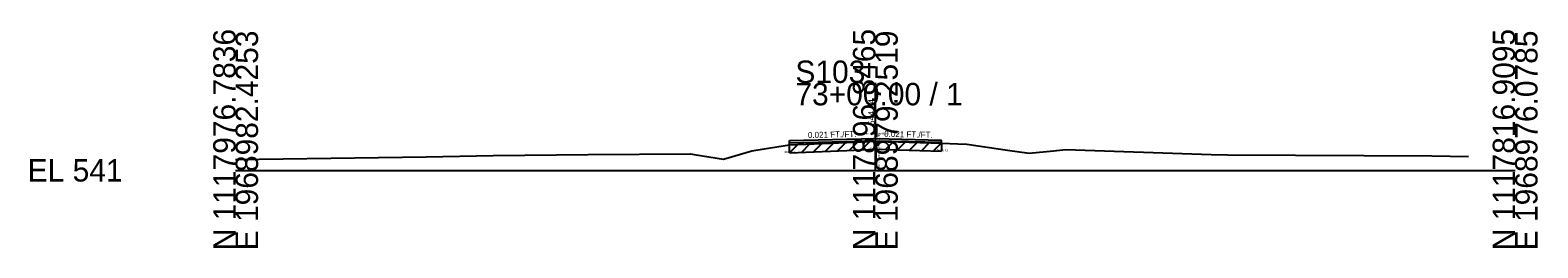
# Model space of a CAD drawing. Extents: x -26 to 163, y -10 to 24018.
# Drawn here: x -25.7 to 162.8, y 20990.3 to 21017.5 of the extents above; entities that cross this region are included whole.
import ezdxf

# ---------------------------------------------------------------- set-up
doc = ezdxf.new("R2010")
doc.units = 0
for name, color, linetype in [('RD_GPK_XS_Cell', 7, 'Continuous'), ('RD_XS_ExGround', 7, 'Continuous'), ('RD_XS_ExPaveRet', 7, 'Continuous'), ('RD_XS_Misc_Line', 7, 'Continuous'), ('RD_XS_PaveOvlay_CP', 7, 'Continuous'), ('RD_XS_TX_Elev_EX', 7, 'Continuous'), ('RD_XS_TX_ExEOP', 7, 'Continuous'), ('RD_XS_TX_Notes', 7, 'Continuous'), ('RD_XS_TX_Profile', 7, 'Continuous'), ('RD_XS_TX_Slope', 7, 'Continuous')]:
    doc.layers.add(name, color=color, linetype=linetype)

msp = doc.modelspace()

# ---------------------------------------------------------------- linework, layer by layer
at = {"layer": 'RD_GPK_XS_Cell'}
for p, q in [((80, 21000), (80, 21010.93)), ((0, 21000), (80, 21000)), ((80, 21000), (160, 21000))]:
    msp.add_line(p, q, dxfattribs=at)
at = {"layer": 'RD_XS_ExGround'}
msp.add_lwpolyline([(0, 21001.37), (23.84, 21001.68), (32.19, 21001.85), (44.07, 21002), (56.87, 21002.06), (57.32, 21001.99), (61.01, 21001.38), (63.14, 21002.03), (64.57, 21002.45), (66.11, 21002.69), (69.26, 21003.19), (76.42, 21003.49), (80.06, 21003.64), (82.83, 21003.55), (88.27, 21003.39), (90.33, 21003.32), (91.43, 21003.27), (96.53, 21002.53), (99.25, 21002.13), (102.29, 21002.44), (103.8, 21002.6), (121.99, 21001.98), (124.04, 21001.92), (149.6, 21001.8), (154.17, 21001.73)], dxfattribs=at)
at = {"layer": 'RD_XS_ExPaveRet'}
for p, q in [((69.26, 21002.19), (70.3, 21003.23)), ((69.26, 21002.19), (69.26, 21003.19)), ((70.76, 21002.25), (71.8, 21003.3)), ((72.26, 21002.32), (73.3, 21003.36)), ((73.76, 21002.38), (74.8, 21003.43)), ((75.26, 21002.45), (76.3, 21003.49)), ((76.42, 21002.49), (80.06, 21002.64)), ((76.76, 21002.51), (77.8, 21003.55)), ((78.26, 21002.57), (79.3, 21003.61)), ((79.76, 21002.63), (80.75, 21003.62)), ((80.06, 21002.64), (82.83, 21002.55)), ((81.26, 21002.61), (82.23, 21003.57)), ((82.76, 21002.56), (83.73, 21003.53)), ((82.83, 21002.55), (88.27, 21002.39)), ((84.26, 21002.51), (85.23, 21003.48)), ((85.76, 21002.46), (86.73, 21003.43)), ((87.26, 21002.42), (88.23, 21003.39)), ((88.27, 21003.39), (88.27, 21002.39)), ((69.26, 21002.19), (76.42, 21002.49))]:
    msp.add_line(p, q, dxfattribs=at)
at = {"layer": 'RD_XS_Misc_Line'}
msp.add_line((80.06, 21003.64), (80.06, 21000.64), dxfattribs=at)
at = {"layer": 'RD_XS_PaveOvlay_CP'}
for p, q in [((69.26, 21003.74), (80, 21003.97)), ((69.26, 21003.19), (69.26, 21003.74)), ((80, 21003.64), (69.26, 21003.42)), ((80, 21003.97), (88.27, 21003.79)), ((88.27, 21003.47), (80, 21003.64)), ((88.27, 21003.39), (88.27, 21003.79))]:
    msp.add_line(p, q, dxfattribs=at)

# ---------------------------------------------------------------- texts
at = {"layer": 'RD_GPK_XS_Cell'}
for s, p in [('N 1117976.7836', (0, 20990)), ('E 1968982.4253', (2.8, 20990)), ('N 1117896.8465', (80, 20990)), ('E 1968979.2519', (82.8, 20990)), ('N 1117816.9095', (160, 20990)), ('E 1968976.0785', (162.8, 20990))]:
    msp.add_text(s, height=2.8, rotation=90, dxfattribs=at).set_placement(p)
for s, p in [('S103', (70, 21010.93)), ('73+00.00 / 1', (70, 21008.13)), ('EL 541', (-26, 20998.6))]:
    msp.add_text(s, height=2.8, dxfattribs=at).set_placement(p)
at = {"layer": 'RD_XS_TX_Elev_EX'}
msp.add_text('544.64', height=0.8, rotation=90, dxfattribs=at).set_placement((79.9, 21005.64))
at = {"layer": 'RD_XS_TX_ExEOP'}
for s, p in [('EOP-L', (69.21, 21003.74)), ('EOP-R', (88.22, 21003.79))]:
    msp.add_text(s, height=0.1, rotation=270, dxfattribs=at).set_placement(p)
at = {"layer": 'RD_XS_TX_Notes'}
for s, p in [('Elev. @CL = 544.97', (78.48, 21004.47)), (' dE= 0.32', (79.29, 21002.64)), (' dE= 0.41', (87.57, 21002.39)), (' dE= 0.55', (68.55, 21002.19))]:
    msp.add_text(s, height=0.25, dxfattribs=at).set_placement(p)
msp.add_text(' Min. Distance @CP = -0.00', height=0.25, rotation=270, dxfattribs=at).set_placement((80.31, 21004.74))
at = {"layer": 'RD_XS_TX_Profile'}
msp.add_text('CL', height=0.25, dxfattribs=at).set_placement((79.77, 21003.97))
at = {"layer": 'RD_XS_TX_Slope'}
for rotation, p in [(1.1916, (71.57, 21004.04)), (358.8084, (81.09, 21004.19))]:
    msp.add_text('0.021 FT./FT.', height=0.75, rotation=rotation, dxfattribs=at).set_placement(p)

doc.saveas('drawing.dxf')
